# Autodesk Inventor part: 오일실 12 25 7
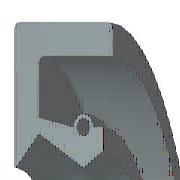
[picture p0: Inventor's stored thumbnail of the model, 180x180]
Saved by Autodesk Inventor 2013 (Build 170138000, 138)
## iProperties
IsCustomPart: 1
Created: 2012-02
Part Number: 오일실 12 25 7
Material: 고무
Description: 오일-실
Document SubType Name: Modeling
Standard: KS B 2804
Designer: test
Standards Organization: KS
Language: ko-KR
Size Designation: D - 12 25 7
Categories: <MemberInstance><Categories><Category DisplayName="샤프트 부품" InternalName="7f7aeb1f-a693-4053-b835-cee3144e0d98" Mnemonic="SHFT"><Category DisplayName="실링" Intern
Density: 0.93 g/cm^3
Author: test
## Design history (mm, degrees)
revolve "본체" stored, may be unused: angle "d17" = 90 deg
revolve "스프링1" stored, may be unused: angle "d18" = 90 deg
body "Solid1"
sketch "스케치1"
  geometry: L1 (0, 12.5)-(7, 12.5); L2 (7, 10.75)-(1.75, 10.75); L3 (1.75, 7.75)-(4.9, 6); L4 (4.9, 6)-(0, 6); L5 (0, 0)-(9.586, 0) reference; L6 (4.9, 6)-(6.3, 6.875); L7 (0, 18)-(0, -3) reference; L8 (-1.941, 0)-(11.507, 0) reference; L9 (4.2, 8.1)-(1.75, 8.59); L10 (1.75, 8.59)-(1.75, 10.75); L11 (0, 12.5)-(0, 6.088); L12 (4.9, 6)-(0, 6); L13 (1.75, 7.75)-(0.152, 6.028); L14 (7, 12.5)-(7, 10.75); L15 (5.6, 8.1)-(6.3, 8.1); L16 (6.3, 8.1)-(6.3, 6.875); C1 r 0.455 at (4.9, 8.1); A1 r 0.7 centre (4.9, 8.1) between (5.6, 8.1) and (4.2, 8.1); A2 r 0.088 centre (0.088, 6.088) between (0, 6.088) and (0.152, 6.028); 1 further point
  constraints: 28 end point, 5 horizontal alignment, 5 point on line, 4 point on circle, 4 vertical alignment, 3 centre point, 3 tangent, 2 collinear, 2 horizontal, 2 perpendicular, 1 coincident, 1 parallel
  dimensions: "d0" = 25 diameter of L1 L5 (= SD2); "d1" = 1.75 distance of L1.end L2.start (= SD); "d2" = 0.91 diameter of C1 (= SPDI); "d3" = 1.4 diameter of A1 (= SPDA); "d4" = 12 diameter of L3.end L5 (= NND); "d5" = 15.5 diameter of L3.start L5 (= TKDM); "d7" = 17.18 diameter of L9.end L5 (= TKDM + 0.24 x SWDT); "d8" = 1.75 distance between parallel lines of L11 L10 (= SD); "d9" = 4.9 distance from line of L11 C1.centre (= SPDST); "d10" = 16.2 diameter of C1.centre L5 (= HLDM); "d11" = 0.0875 radius of A2 (= 0.25 x LAB); "d12" = 6.3 distance between parallel lines of L11 L16 (= SDI); "d13" = 13.75 diameter of L6.end L5 (= ABDM); "d14" = 7 distance from line of L11 L1.end (= SWDT)
fillet "모깎기1" dims "d6" = 0.3 (= RR)
other parameters: "SD2" = 25 [user parameter; used in 1 equation term], "SWDT" = 7 [user parameter; used in 2 equation terms], "RR" = 0.3 [user parameter; used in 1 equation term], "SD" = 1.75 [user parameter; used in 2 equation terms], "NND" = 12 [user parameter; used in 1 equation term], "SPDA" = 1.4 [user parameter; used in 1 equation term], "SPDI" = 0.91 [user parameter; used in 1 equation term], "TKDM" = 15.5 [user parameter; used in 2 equation terms], "HLDM" = 16.2 [user parameter; used in 1 equation term], "ABDM" = 13.75 [user parameter; used in 1 equation term], "SDI" = 6.3 [user parameter; used in 1 equation term], "SPDST" = 4.9 [user parameter; used in 1 equation term], "LAB" = 0.35 [user parameter; used in 1 equation term], "d15" = 0, "d16" = 0, "d19" = 0
